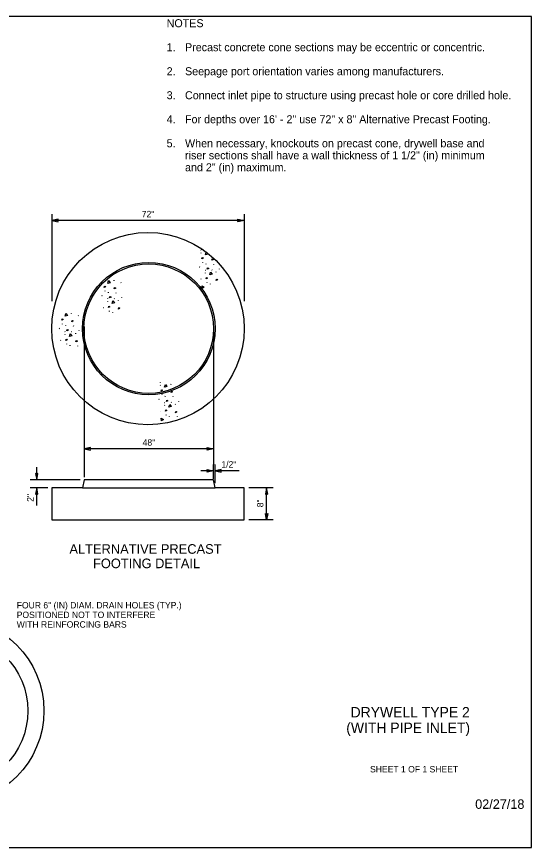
# Model space of a CAD drawing. Extents: x 99862 to 103151, y 100000 to 102076.
# Drawn here: x 101866 to 103151, y 100000 to 102076 of the extents above; entities that cross this region are included whole.
import ezdxf

# ---------------------------------------------------------------- set-up
doc = ezdxf.new("R2010")
doc.units = 0
for name, color, linetype in [('Level 1', 7, 'Continuous'), ('Level 14', 7, 'Continuous'), ('Level 15', 7, 'Continuous'), ('Level 16', 7, 'Continuous'), ('Level 17', 7, 'Continuous'), ('Level 20', 7, 'Continuous'), ('Level 60', 7, 'Continuous'), ('Level 62', 7, 'Continuous')]:
    doc.layers.add(name, color=color, linetype=linetype)

msp = doc.modelspace()

# ---------------------------------------------------------------- linework, layer by layer
at = {"layer": 'Level 1'}
msp.add_lwpolyline([(99862, 99999.5), (103151, 99999.5), (103151, 102075.5), (99862, 102075.5)], close=True, dxfattribs=at)
at = {"layer": 'Level 14'}
for p, q in [((102505.9, 100897.9), (102445.9, 100897.9)), ((102505.9, 100817.9), (102445.9, 100817.9))]:
    msp.add_line(p, q, dxfattribs=at)
at = {"layer": 'Level 15'}
for p, q in [((101953.3, 101582.1), (101953.3, 101364.8)), ((102433.9, 101582.1), (102433.9, 101364.8)), ((102433.9, 101566.1), (101953.3, 101566.1)), ((102034.1, 101301.1), (102034.1, 100924.9)), ((102357.3, 101300.2), (102357.3, 100956.6)), ((102357.3, 100995.4), (102034.1, 100995.4)), ((102357.3, 100920.6), (102357.3, 100956.6)), ((102361.1, 100909.9), (102361.1, 100956.6)), ((101915.9, 100917.9), (101915.9, 100949.9)), ((102357.3, 100940.6), (102325.3, 100940.6)), ((102421.6, 100940.6), (102361.1, 100940.6)), ((102024.6, 100917.9), (101899.9, 100917.9)), ((101943.9, 100897.9), (101899.9, 100897.9)), ((101915.9, 100853.8), (101915.9, 100897.9)), ((102505.9, 100897.9), (102445.9, 100897.9)), ((102489.9, 100817.9), (102489.9, 100897.9))]:
    msp.add_line(p, q, dxfattribs=at)
for points in [[(101953.3, 101566.1), (101969, 101563), (101968.3, 101566.1), (101969, 101569.2)], [(102433.9, 101566.1), (102418.2, 101563), (102418.9, 101566.1), (102418.2, 101569.2)], [(102034.1, 100995.4), (102049.8, 100992.3), (102049.1, 100995.4), (102049.8, 100998.4)], [(102357.3, 100995.4), (102341.6, 100992.3), (102342.3, 100995.4), (102341.6, 100998.4)], [(102357.3, 100940.6), (102341.6, 100937.5), (102342.3, 100940.6), (102341.6, 100943.7)], [(102361.1, 100940.6), (102376.8, 100937.5), (102376.1, 100940.6), (102376.8, 100943.7)], [(101915.9, 100917.9), (101919, 100933.6), (101915.9, 100932.9), (101912.8, 100933.6)], [(101915.9, 100897.9), (101912.8, 100882.1), (101915.9, 100882.9), (101919, 100882.1)], [(102489.9, 100897.9), (102486.8, 100882.1), (102489.9, 100882.9), (102493, 100882.1)], [(102489.9, 100817.9), (102486.8, 100833.6), (102489.9, 100832.9), (102493, 100833.6)]]:
    msp.add_lwpolyline(points, close=True, dxfattribs=at)
at = {"layer": 'Level 16'}
for p, q in [((102325.5, 101492.5), (102326.2, 101491.9)), ((102326.3, 101484.3), (102326.6, 101485.5)), ((102329.7, 101461.8), (102330.1, 101460.7)), ((102338.7, 101456.9), (102338.9, 101458.1)), ((102358.2, 101455.9), (102358.5, 101457.1)), ((102336.2, 101442.2), (102336.9, 101441.6)), ((102337, 101434), (102337.3, 101435.2)), ((102353.3, 101442.6), (102353.9, 101442)), ((102363.6, 101436.7), (102363.8, 101437.9)), ((102372.3, 101444.1), (102372.4, 101444.9)), ((102109, 101415.6), (102109.2, 101416.8)), ((102325.6, 101420.5), (102326.3, 101419.9)), ((102125.8, 101411), (102126.5, 101410.4)), ((102340.4, 101411.5), (102340.8, 101410.4)), ((102349.4, 101406.6), (102349.6, 101407.8)), ((102085.8, 101390.3), (102086.2, 101389.2)), ((102094.8, 101385.5), (102095, 101386.7)), ((102109.4, 101371.1), (102110, 101370.5)), ((102114.3, 101384.4), (102114.6, 101385.6)), ((102128.4, 101372.7), (102128.5, 101373.4)), ((102092.3, 101370.7), (102093, 101370.1)), ((102093.1, 101362.5), (102093.4, 101363.7)), ((102119.7, 101365.2), (102119.9, 101366.4)), ((102002.6, 101333.4), (102002.9, 101334.6)), ((102081.7, 101349), (102082.4, 101348.4)), ((102096.5, 101340), (102096.9, 101338.9)), ((102105.5, 101335.1), (102105.7, 101336.3)), ((102019.5, 101328.8), (102020.1, 101328.2)), ((101979.5, 101308.1), (101979.8, 101307)), ((101986, 101288.5), (101986.6, 101287.9)), ((101988.4, 101303.3), (101988.7, 101304.5)), ((102003, 101288.9), (102003.7, 101288.3)), ((102008, 101302.2), (102008.2, 101303.4)), ((102022, 101290.5), (102022.2, 101291.2)), ((101986.8, 101280.3), (101987, 101281.5)), ((102013.3, 101283), (102013.6, 101284.2)), ((101975.4, 101266.8), (101976, 101266.2)), ((101990.2, 101257.8), (101990.5, 101256.7)), ((101999.1, 101252.9), (101999.4, 101254.1)), ((102018.7, 101251.9), (102018.9, 101253.1)), ((102223.7, 101161.9), (102224.3, 101161.3)), ((102224.5, 101153.7), (102224.7, 101154.9)), ((102251, 101156.5), (102251.3, 101157.7)), ((102227.9, 101131.2), (102228.2, 101130.1)), ((102236.8, 101126.4), (102237.1, 101127.6)), ((102256.4, 101125.3), (102256.6, 101126.5)), ((102234.4, 101111.6), (102235, 101111)), ((102235.2, 101103.4), (102235.4, 101104.6)), ((102251.4, 101112), (102252.1, 101111.4)), ((102261.7, 101106.1), (102262, 101107.3)), ((102270.4, 101113.6), (102270.6, 101114.3)), ((102223.8, 101089.9), (102224.4, 101089.3)), ((102238.6, 101080.9), (102238.9, 101079.8)), ((102247.5, 101076), (102247.8, 101077.2)), ((102267.1, 101075), (102267.3, 101076.2))]:
    msp.add_line(p, q, dxfattribs=at)
for points in [[(102337.2, 101480.3), (102339.1, 101487.2), (102342.9, 101482), (102337.3, 101480.3)], [(102328.4, 101470.4), (102329.2, 101473.7), (102332, 101472.4), (102328.4, 101470.4)], [(102353.4, 101466.6), (102354.2, 101470), (102357.1, 101468.7), (102353.4, 101466.6)], [(102322.4, 101450.3), (102323.3, 101449.7), (102322.4, 101449.1)], [(102341.6, 101444.2), (102342.4, 101447.6), (102345.3, 101446.3), (102341.6, 101444.2)], [(102347.8, 101429.9), (102349.8, 101436.8), (102353.6, 101431.7), (102348, 101430)], [(102093.2, 101408.8), (102095.2, 101415.7), (102099, 101410.5), (102093.4, 101408.8)], [(102339.1, 101420.1), (102339.9, 101423.4), (102342.7, 101422.1), (102339.1, 101420.1)], [(102364.1, 101416.3), (102364.9, 101419.6), (102367.8, 101418.3), (102364.1, 101416.3)], [(102084.5, 101398.9), (102085.3, 101402.3), (102088.1, 101401), (102084.5, 101398.9)], [(102109.5, 101395.1), (102110.3, 101398.5), (102113.1, 101397.2), (102109.5, 101395.1)], [(102329.2, 101395.8), (102328.7, 101403), (102334, 101399.4), (102329.3, 101395.9)], [(102078.5, 101378.8), (102079.4, 101378.2), (102078.5, 101377.6)], [(102097.7, 101372.8), (102098.5, 101376.1), (102101.4, 101374.8), (102097.7, 101372.8)], [(102095.2, 101348.6), (102096, 101351.9), (102098.8, 101350.6), (102095.2, 101348.6)], [(102103.9, 101358.5), (102105.9, 101365.4), (102109.7, 101360.2), (102104.1, 101358.5)], [(101986.9, 101326.6), (101988.9, 101333.5), (101992.6, 101328.3), (101987, 101326.6)], [(102120.2, 101344.8), (102121, 101348.2), (102123.8, 101346.9), (102120.2, 101344.8)], [(101978.2, 101316.7), (101979, 101320.1), (101981.8, 101318.8), (101978.2, 101316.7)], [(102003.2, 101313), (102004, 101316.3), (102006.8, 101315), (102003.2, 101313)], [(101972.2, 101296.6), (101973.1, 101296), (101972.2, 101295.4)], [(101991.4, 101290.6), (101992.2, 101293.9), (101995, 101292.6), (101991.4, 101290.6)], [(101988.8, 101266.4), (101989.7, 101269.7), (101992.5, 101268.4), (101988.8, 101266.4)], [(101997.6, 101276.3), (101999.6, 101283.2), (102003.3, 101278), (101997.7, 101276.3)], [(102013.9, 101262.6), (102014.7, 101266), (102017.5, 101264.7), (102013.9, 101262.6)], [(102226.5, 101139.8), (102227.3, 101143.2), (102230.2, 101141.9), (102226.5, 101139.8)], [(102235.3, 101149.7), (102237.3, 101156.6), (102241, 101151.4), (102235.4, 101149.7)], [(102251.6, 101136), (102252.4, 101139.4), (102255.2, 101138.1), (102251.6, 101136)], [(102220.6, 101119.7), (102221.4, 101119.1), (102220.6, 101118.5)], [(102239.8, 101113.6), (102240.6, 101117), (102243.4, 101115.7), (102239.8, 101113.6)], [(102246, 101099.4), (102248, 101106.2), (102251.7, 101101.1), (102246.1, 101099.4)], [(102237.2, 101089.5), (102238, 101092.8), (102240.9, 101091.5), (102237.2, 101089.5)], [(102262.3, 101085.7), (102263.1, 101089.1), (102265.9, 101087.8), (102262.3, 101085.7)], [(102227.3, 101065.2), (102226.8, 101072.4), (102232.1, 101068.8), (102227.5, 101065.3)]]:
    msp.add_lwpolyline(points, dxfattribs=at)
at = {"layer": 'Level 17'}
msp.add_line((102030.1, 100897.9), (102361.1, 100897.9), dxfattribs=at)
msp.add_lwpolyline([(102357.2, 100917.9), (102034, 100917.9), (102030.1, 100897.9), (101953.3, 100897.9), (101953.3, 100817.9), (102433.9, 100817.9), (102433.9, 100897.9), (102361.1, 100897.9)], close=True, dxfattribs=at)
for centre, radius in [((102193.6, 101295.8), 240.3), ((102195.6, 101295.8), 165.5), ((102195.6, 101295.8), 161.7), ((101701.9, 100340.8), 232), ((101701.4, 100340.8), 192.4)]:
    msp.add_circle(centre, radius, dxfattribs=at)
at = {"layer": 'Level 60'}
msp.add_line((103151, 102075.5), (103151, 102075.5), dxfattribs=at)
msp.add_line((103151, 102075.5), (103151, 102075.5), dxfattribs=at)
msp.add_line((103151, 102075.5), (103151, 102075.5), dxfattribs=at)
msp.add_line((103151, 102075.5), (103151, 102075.5), dxfattribs=at)

# ---------------------------------------------------------------- texts
at = {"layer": 'Level 15'}
msp.add_text('02/27/18', height=23.62, dxfattribs=at).set_placement((103010.7, 100095.8))
at = {"layer": 'Level 20'}
for s, height, p in [('NOTES', 20, (102240.3, 102049)), ('1.', 20, (102240.3, 101989)), ('Precast concrete cone sections may be eccentric or concentric.', 20, (102286.2, 101989)), ('2.', 20, (102240.3, 101929)), ('Seepage port orientation varies among manufacturers.', 20, (102286.2, 101929)), ('3.', 20, (102240.3, 101869)), ('Connect inlet pipe to structure using precast hole or core drilled hole.', 20, (102286.2, 101869)), ('4.', 20, (102240.3, 101809)), ('For depths over 16\' - 2" use 72" x 8" Alternative Precast Footing.', 20, (102286.2, 101809)), ('5.', 20, (102240.3, 101749)), ('When necessary, knockouts on precast cone, drywell base and ', 20, (102286.2, 101749)), ('riser sections shall have a wall thickness of 1 1/2" (in) minimum ', 20, (102286.2, 101719)), ('and 2" (in) maximum.', 20, (102286.2, 101689)), ('72"', 16, (102178.2, 101574.1)), ('48"', 16, (102180.3, 101003.4)), ('1/2"', 16, (102377, 100948.6)), ('ALTERNATIVE PRECAST', 24, (101997.5, 100733.2)), ('FOOTING DETAIL', 24, (102056.4, 100697.2)), ('FOUR 6" (IN) DIAM. DRAIN HOLES (TYP.) ', 16, (101865.9, 100596.6)), ('POSITIONED NOT TO INTERFERE', 16, (101865.9, 100572.6)), ('WITH REINFORCING BARS', 16, (101865.9, 100548.6))]:
    msp.add_text(s, height=height, dxfattribs=at).set_placement(p)
for s, p in [('2"', (101907.9, 100863.1)), ('8"', (102481.9, 100849.4))]:
    msp.add_text(s, height=16, rotation=90, dxfattribs=at).set_placement(p)
at = {"layer": 'Level 62'}
for s, height, p in [('DRYWELL TYPE 2', 26, (102699.6, 100324.3)), ('(WITH PIPE INLET)', 26, (102688.8, 100285.3)), ('SHEET 1 OF 1 SHEET', 16, (102748.2, 100186.8))]:
    msp.add_text(s, height=height, dxfattribs=at).set_placement(p)

doc.saveas('drawing.dxf')
